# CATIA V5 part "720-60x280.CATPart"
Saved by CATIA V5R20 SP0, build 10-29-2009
Part number: 720-60x280
Definition: NONE
Nomenclature: 720-60x280
Source: Unknown
Description: 720-60x280
Bounding box of the stored display mesh (mm): x 0 to 280, y -30 to 30, z -30 to 30
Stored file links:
  C:\Users\Utente\Desktop\IO LAVORO\3D X SITO CF\X SITO\720\720-60x280.CATPart
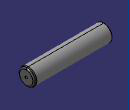
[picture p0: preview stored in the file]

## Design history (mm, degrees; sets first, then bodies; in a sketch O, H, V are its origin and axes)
Body1 "720-60x280" (main body)
  Solid1: solid without history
